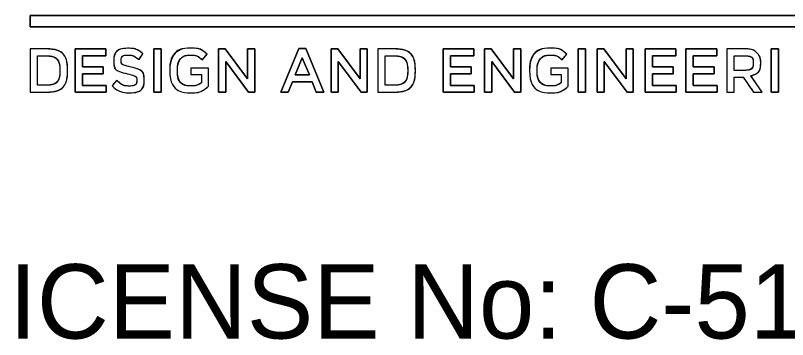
# Model space of a CAD drawing. Extents: x 1674550 to 1676250, y 1328139 to 1330492.
# Drawn here: x 1676168.88 to 1676209.45, y 1329059.45 to 1329076.5 of the extents above; entities that cross this region are included whole.
import ezdxf

# ---------------------------------------------------------------- set-up
doc = ezdxf.new("R2010")
doc.units = 0
doc.layers.add('Sheet Plan CELL', color=7, linetype='Continuous')

msp = doc.modelspace()

# ---------------------------------------------------------------- linework, layer by layer
at = {"layer": 'Sheet Plan CELL'}
for p, q in [((1676175.371, 1329074.182), (1676175.577, 1329074.484)), ((1676178.701, 1329074.166), (1676178.943, 1329074.467)), ((1676197.607, 1329074.166), (1676197.85, 1329074.467)), ((1676174.042, 1329074.11), (1676174.042, 1329074.104)), ((1676174.425, 1329074.14), (1676174.425, 1329074.146)), ((1676207.647, 1329073.997), (1676207.647, 1329073.99)), ((1676208.036, 1329074.013), (1676208.036, 1329074.02)), ((1676171.214, 1329073.601), (1676171.214, 1329073.595)), ((1676171.616, 1329073.601), (1676171.616, 1329073.607)), ((1676176.983, 1329073.601), (1676176.983, 1329073.595)), ((1676177.384, 1329073.601), (1676177.384, 1329073.607)), ((1676189.488, 1329073.601), (1676189.488, 1329073.595)), ((1676189.89, 1329073.601), (1676189.89, 1329073.607)), ((1676195.889, 1329073.601), (1676195.889, 1329073.595)), ((1676196.29, 1329073.601), (1676196.29, 1329073.607)), ((1676174.185, 1329073.082), (1676173.955, 1329072.796)), ((1676175.259, 1329073.079), (1676175.259, 1329073.072)), ((1676175.642, 1329073.111), (1676175.642, 1329073.118))]:
    msp.add_line(p, q, dxfattribs=at)
for points in [[(1676230.5, 1329075.895), (1676169.657, 1329075.895), (1676169.657, 1329076.499), (1676230.5, 1329076.499), (1676230.5, 1329075.895)], [(1676230.5, 1329076.499), (1676169.657, 1329076.499), (1676169.657, 1329075.895), (1676230.5, 1329075.895), (1676230.5, 1329076.499)], [(1676183.775, 1329074.753), (1676184.13, 1329074.753), (1676185.089, 1329072.465), (1676184.684, 1329072.465), (1676184.463, 1329073.014), (1676183.433, 1329073.014), (1676183.209, 1329072.465), (1676182.817, 1329072.465), (1676183.775, 1329074.753)], [(1676182.817, 1329072.465), (1676183.209, 1329072.465), (1676183.433, 1329073.014), (1676184.463, 1329073.014), (1676184.684, 1329072.465), (1676185.089, 1329072.465), (1676184.13, 1329074.753), (1676183.775, 1329074.753), (1676182.817, 1329072.465)], [(1676170.458, 1329074.737), (1676169.646, 1329074.737), (1676169.646, 1329072.465), (1676170.458, 1329072.465)], [(1676170.458, 1329072.829), (1676170.029, 1329072.829), (1676170.029, 1329074.373), (1676170.458, 1329074.373)], [(1676172.017, 1329074.737), (1676173.632, 1329074.737), (1676173.632, 1329074.38), (1676172.399, 1329074.38), (1676172.399, 1329073.789), (1676173.492, 1329073.789), (1676173.492, 1329073.432), (1676172.399, 1329073.432), (1676172.399, 1329072.822), (1676173.647, 1329072.822), (1676173.647, 1329072.465), (1676172.017, 1329072.465), (1676172.017, 1329074.737)], [(1676172.017, 1329072.465), (1676173.647, 1329072.465), (1676173.647, 1329072.822), (1676172.399, 1329072.822), (1676172.399, 1329073.432), (1676173.492, 1329073.432), (1676173.492, 1329073.789), (1676172.399, 1329073.789), (1676172.399, 1329074.38), (1676173.632, 1329074.38), (1676173.632, 1329074.737), (1676172.017, 1329074.737), (1676172.017, 1329072.465)], [(1676176.145, 1329074.737), (1676176.528, 1329074.737), (1676176.528, 1329072.465), (1676176.145, 1329072.465), (1676176.145, 1329074.737)], [(1676176.145, 1329072.465), (1676176.528, 1329072.465), (1676176.528, 1329074.737), (1676176.145, 1329074.737), (1676176.145, 1329072.465)], [(1676179.55, 1329074.737), (1676179.904, 1329074.737), (1676181.072, 1329073.166), (1676181.072, 1329074.737), (1676181.448, 1329074.737), (1676181.448, 1329072.465), (1676181.127, 1329072.465), (1676179.926, 1329074.081), (1676179.926, 1329072.465), (1676179.55, 1329072.465), (1676179.55, 1329074.737)], [(1676179.55, 1329072.465), (1676179.926, 1329072.465), (1676179.926, 1329074.081), (1676181.127, 1329072.465), (1676181.448, 1329072.465), (1676181.448, 1329074.737), (1676181.072, 1329074.737), (1676181.072, 1329073.166), (1676179.904, 1329074.737), (1676179.55, 1329074.737), (1676179.55, 1329072.465)], [(1676185.462, 1329074.737), (1676185.817, 1329074.737), (1676186.983, 1329073.166), (1676186.983, 1329074.737), (1676187.36, 1329074.737), (1676187.36, 1329072.465), (1676187.04, 1329072.465), (1676185.838, 1329074.081), (1676185.838, 1329072.465), (1676185.462, 1329072.465), (1676185.462, 1329074.737)], [(1676185.462, 1329072.465), (1676185.838, 1329072.465), (1676185.838, 1329074.081), (1676187.04, 1329072.465), (1676187.36, 1329072.465), (1676187.36, 1329074.737), (1676186.983, 1329074.737), (1676186.983, 1329073.166), (1676185.817, 1329074.737), (1676185.462, 1329074.737), (1676185.462, 1329072.465)], [(1676188.732, 1329074.737), (1676187.92, 1329074.737), (1676187.92, 1329072.465), (1676188.732, 1329072.465)], [(1676188.732, 1329072.829), (1676188.303, 1329072.829), (1676188.303, 1329074.373), (1676188.732, 1329074.373)], [(1676191.349, 1329074.737), (1676192.964, 1329074.737), (1676192.964, 1329074.38), (1676191.732, 1329074.38), (1676191.732, 1329073.789), (1676192.824, 1329073.789), (1676192.824, 1329073.432), (1676191.732, 1329073.432), (1676191.732, 1329072.822), (1676192.98, 1329072.822), (1676192.98, 1329072.465), (1676191.349, 1329072.465), (1676191.349, 1329074.737)], [(1676191.349, 1329072.465), (1676192.98, 1329072.465), (1676192.98, 1329072.822), (1676191.732, 1329072.822), (1676191.732, 1329073.432), (1676192.824, 1329073.432), (1676192.824, 1329073.789), (1676191.732, 1329073.789), (1676191.732, 1329074.38), (1676192.964, 1329074.38), (1676192.964, 1329074.737), (1676191.349, 1329074.737), (1676191.349, 1329072.465)], [(1676193.527, 1329074.737), (1676193.882, 1329074.737), (1676195.049, 1329073.166), (1676195.049, 1329074.737), (1676195.425, 1329074.737), (1676195.425, 1329072.465), (1676195.105, 1329072.465), (1676193.904, 1329074.081), (1676193.904, 1329072.465), (1676193.527, 1329072.465), (1676193.527, 1329074.737)], [(1676193.527, 1329072.465), (1676193.904, 1329072.465), (1676193.904, 1329074.081), (1676195.105, 1329072.465), (1676195.425, 1329072.465), (1676195.425, 1329074.737), (1676195.049, 1329074.737), (1676195.049, 1329073.166), (1676193.882, 1329074.737), (1676193.527, 1329074.737), (1676193.527, 1329072.465)], [(1676198.446, 1329074.737), (1676198.829, 1329074.737), (1676198.829, 1329072.465), (1676198.446, 1329072.465), (1676198.446, 1329074.737)], [(1676198.446, 1329072.465), (1676198.829, 1329072.465), (1676198.829, 1329074.737), (1676198.446, 1329074.737), (1676198.446, 1329072.465)], [(1676199.442, 1329074.737), (1676199.797, 1329074.737), (1676200.964, 1329073.166), (1676200.964, 1329074.737), (1676201.341, 1329074.737), (1676201.341, 1329072.465), (1676201.02, 1329072.465), (1676199.819, 1329074.081), (1676199.819, 1329072.465), (1676199.442, 1329072.465), (1676199.442, 1329074.737)], [(1676199.442, 1329072.465), (1676199.819, 1329072.465), (1676199.819, 1329074.081), (1676201.02, 1329072.465), (1676201.341, 1329072.465), (1676201.341, 1329074.737), (1676200.964, 1329074.737), (1676200.964, 1329073.166), (1676199.797, 1329074.737), (1676199.442, 1329074.737), (1676199.442, 1329072.465)], [(1676201.962, 1329074.737), (1676203.578, 1329074.737), (1676203.578, 1329074.38), (1676202.345, 1329074.38), (1676202.345, 1329073.789), (1676203.438, 1329073.789), (1676203.438, 1329073.432), (1676202.345, 1329073.432), (1676202.345, 1329072.822), (1676203.593, 1329072.822), (1676203.593, 1329072.465), (1676201.962, 1329072.465), (1676201.962, 1329074.737)], [(1676201.962, 1329072.465), (1676203.593, 1329072.465), (1676203.593, 1329072.822), (1676202.345, 1329072.822), (1676202.345, 1329073.432), (1676203.438, 1329073.432), (1676203.438, 1329073.789), (1676202.345, 1329073.789), (1676202.345, 1329074.38), (1676203.578, 1329074.38), (1676203.578, 1329074.737), (1676201.962, 1329074.737), (1676201.962, 1329072.465)], [(1676204.109, 1329074.737), (1676205.724, 1329074.737), (1676205.724, 1329074.38), (1676204.492, 1329074.38), (1676204.492, 1329073.789), (1676205.585, 1329073.789), (1676205.585, 1329073.432), (1676204.492, 1329073.432), (1676204.492, 1329072.822), (1676205.74, 1329072.822), (1676205.74, 1329072.465), (1676204.109, 1329072.465), (1676204.109, 1329074.737)], [(1676204.109, 1329072.465), (1676205.74, 1329072.465), (1676205.74, 1329072.822), (1676204.492, 1329072.822), (1676204.492, 1329073.432), (1676205.585, 1329073.432), (1676205.585, 1329073.789), (1676204.492, 1329073.789), (1676204.492, 1329074.38), (1676205.724, 1329074.38), (1676205.724, 1329074.737), (1676204.109, 1329074.737), (1676204.109, 1329072.465)], [(1676207.227, 1329074.737), (1676206.256, 1329074.737), (1676206.256, 1329072.465), (1676206.639, 1329072.465), (1676206.639, 1329073.257), (1676207.118, 1329073.257), (1676207.654, 1329072.465), (1676208.108, 1329072.465), (1676207.52, 1329073.325)], [(1676207.199, 1329073.611), (1676206.639, 1329073.611), (1676206.639, 1329074.373), (1676207.196, 1329074.373)], [(1676208.59, 1329074.737), (1676208.972, 1329074.737), (1676208.972, 1329072.465), (1676208.59, 1329072.465), (1676208.59, 1329074.737)], [(1676208.59, 1329072.465), (1676208.972, 1329072.465), (1676208.972, 1329074.737), (1676208.59, 1329074.737), (1676208.59, 1329072.465)], [(1676184.323, 1329073.367), (1676183.947, 1329074.276), (1676183.573, 1329073.367), (1676184.323, 1329073.367)], [(1676183.573, 1329073.367), (1676183.947, 1329074.276), (1676184.323, 1329073.367), (1676183.573, 1329073.367)], [(1676179.021, 1329072.78), (1676179.021, 1329073.734), (1676178.094, 1329073.734), (1676178.094, 1329073.387), (1676178.651, 1329073.387), (1676178.651, 1329072.962)], [(1676197.927, 1329072.78), (1676197.927, 1329073.734), (1676197, 1329073.734), (1676197, 1329073.387), (1676197.557, 1329073.387), (1676197.557, 1329072.962)]]:
    msp.add_lwpolyline(points, dxfattribs=at)
for points, degree in [([(1676173.955, 1329072.796), (1676173.955, 1329072.796), (1676174.185, 1329073.082), (1676174.185, 1329073.082), (1676174.394, 1329072.894), (1676174.605, 1329072.787), (1676174.873, 1329072.787), (1676175.11, 1329072.787), (1676175.259, 1329072.903), (1676175.259, 1329073.072), (1676175.259, 1329073.072), (1676175.259, 1329073.079), (1676175.259, 1329073.079), (1676175.259, 1329073.241), (1676175.172, 1329073.328), (1676174.767, 1329073.426), (1676174.304, 1329073.543), (1676174.042, 1329073.685), (1676174.042, 1329074.104), (1676174.042, 1329074.104), (1676174.042, 1329074.11), (1676174.042, 1329074.11), (1676174.042, 1329074.5), (1676174.353, 1329074.769), (1676174.786, 1329074.769), (1676175.104, 1329074.769), (1676175.356, 1329074.669), (1676175.577, 1329074.484), (1676175.577, 1329074.484), (1676175.371, 1329074.182), (1676175.371, 1329074.182), (1676175.175, 1329074.334), (1676174.979, 1329074.416), (1676174.78, 1329074.416), (1676174.556, 1329074.416), (1676174.425, 1329074.295), (1676174.425, 1329074.146), (1676174.425, 1329074.146), (1676174.425, 1329074.14), (1676174.425, 1329074.14), (1676174.425, 1329073.964), (1676174.525, 1329073.887), (1676174.945, 1329073.783), (1676175.405, 1329073.666), (1676175.642, 1329073.494), (1676175.642, 1329073.118), (1676175.642, 1329073.118), (1676175.642, 1329073.111), (1676175.642, 1329073.111), (1676175.642, 1329072.686), (1676175.321, 1329072.433), (1676174.864, 1329072.433), (1676174.531, 1329072.433), (1676174.217, 1329072.553), (1676173.955, 1329072.796)], 3), ([(1676175.577, 1329074.484), (1676175.356, 1329074.669), (1676175.104, 1329074.769), (1676174.786, 1329074.769), (1676174.353, 1329074.769), (1676174.042, 1329074.5), (1676174.042, 1329074.11)], 3), ([(1676176.983, 1329073.595), (1676176.983, 1329073.595), (1676176.983, 1329073.601), (1676176.983, 1329073.601), (1676176.983, 1329074.237), (1676177.449, 1329074.776), (1676178.106, 1329074.776), (1676178.486, 1329074.776), (1676178.719, 1329074.665), (1676178.943, 1329074.467), (1676178.943, 1329074.467), (1676178.701, 1329074.166), (1676178.701, 1329074.166), (1676178.532, 1329074.315), (1676178.368, 1329074.409), (1676178.091, 1329074.409), (1676177.689, 1329074.409), (1676177.384, 1329074.042), (1676177.384, 1329073.607), (1676177.384, 1329073.607), (1676177.384, 1329073.601), (1676177.384, 1329073.601), (1676177.384, 1329073.134), (1676177.68, 1329072.79), (1676178.125, 1329072.79), (1676178.33, 1329072.79), (1676178.517, 1329072.858), (1676178.651, 1329072.962), (1676178.651, 1329072.962), (1676178.651, 1329073.387), (1676178.651, 1329073.387), (1676178.651, 1329073.387), (1676178.094, 1329073.387), (1676178.094, 1329073.387), (1676178.094, 1329073.387), (1676178.094, 1329073.734), (1676178.094, 1329073.734), (1676178.094, 1329073.734), (1676179.021, 1329073.734), (1676179.021, 1329073.734), (1676179.021, 1329073.734), (1676179.021, 1329072.78), (1676179.021, 1329072.78), (1676178.806, 1329072.589), (1676178.498, 1329072.426), (1676178.112, 1329072.426), (1676177.431, 1329072.426), (1676176.983, 1329072.933), (1676176.983, 1329073.595)], 3), ([(1676178.943, 1329074.467), (1676178.719, 1329074.665), (1676178.486, 1329074.776), (1676178.106, 1329074.776), (1676177.449, 1329074.776), (1676176.983, 1329074.237), (1676176.983, 1329073.601)], 3), ([(1676195.889, 1329073.595), (1676195.889, 1329073.595), (1676195.889, 1329073.601), (1676195.889, 1329073.601), (1676195.889, 1329074.237), (1676196.356, 1329074.776), (1676197.012, 1329074.776), (1676197.392, 1329074.776), (1676197.625, 1329074.665), (1676197.85, 1329074.467), (1676197.85, 1329074.467), (1676197.607, 1329074.166), (1676197.607, 1329074.166), (1676197.439, 1329074.315), (1676197.274, 1329074.409), (1676196.997, 1329074.409), (1676196.595, 1329074.409), (1676196.29, 1329074.042), (1676196.29, 1329073.607), (1676196.29, 1329073.607), (1676196.29, 1329073.601), (1676196.29, 1329073.601), (1676196.29, 1329073.134), (1676196.586, 1329072.79), (1676197.031, 1329072.79), (1676197.236, 1329072.79), (1676197.423, 1329072.858), (1676197.557, 1329072.962), (1676197.557, 1329072.962), (1676197.557, 1329073.387), (1676197.557, 1329073.387), (1676197.557, 1329073.387), (1676197, 1329073.387), (1676197, 1329073.387), (1676197, 1329073.387), (1676197, 1329073.734), (1676197, 1329073.734), (1676197, 1329073.734), (1676197.927, 1329073.734), (1676197.927, 1329073.734), (1676197.927, 1329073.734), (1676197.927, 1329072.78), (1676197.927, 1329072.78), (1676197.713, 1329072.589), (1676197.404, 1329072.426), (1676197.019, 1329072.426), (1676196.337, 1329072.426), (1676195.889, 1329072.933), (1676195.889, 1329073.595)], 3), ([(1676197.85, 1329074.467), (1676197.625, 1329074.665), (1676197.392, 1329074.776), (1676197.012, 1329074.776), (1676196.356, 1329074.776), (1676195.889, 1329074.237), (1676195.889, 1329073.601)], 3), ([(1676169.646, 1329074.737), (1676169.646, 1329074.737), (1676170.458, 1329074.737), (1676170.458, 1329074.737), (1676171.143, 1329074.737), (1676171.616, 1329074.247), (1676171.616, 1329073.607), (1676171.616, 1329073.607), (1676171.616, 1329073.601), (1676171.616, 1329073.601), (1676171.616, 1329072.962), (1676171.143, 1329072.465), (1676170.458, 1329072.465), (1676170.458, 1329072.465), (1676169.646, 1329072.465), (1676169.646, 1329072.465), (1676169.646, 1329072.465), (1676169.646, 1329074.737), (1676169.646, 1329074.737)], 3), ([(1676170.029, 1329074.373), (1676170.029, 1329074.373), (1676170.029, 1329072.829), (1676170.029, 1329072.829), (1676170.029, 1329072.829), (1676170.458, 1329072.829), (1676170.458, 1329072.829), (1676170.915, 1329072.829), (1676171.214, 1329073.15), (1676171.214, 1329073.595), (1676171.214, 1329073.595), (1676171.214, 1329073.601), (1676171.214, 1329073.601), (1676171.214, 1329074.046), (1676170.915, 1329074.373), (1676170.458, 1329074.373), (1676170.458, 1329074.373), (1676170.029, 1329074.373), (1676170.029, 1329074.373)], 3), ([(1676171.616, 1329073.607), (1676171.616, 1329074.247), (1676171.143, 1329074.737), (1676170.458, 1329074.737)], 2), ([(1676170.458, 1329074.373), (1676170.915, 1329074.373), (1676171.214, 1329074.046), (1676171.214, 1329073.601)], 2), ([(1676174.425, 1329074.146), (1676174.425, 1329074.295), (1676174.556, 1329074.416), (1676174.78, 1329074.416), (1676174.979, 1329074.416), (1676175.175, 1329074.334), (1676175.371, 1329074.182)], 3), ([(1676177.384, 1329073.607), (1676177.384, 1329074.042), (1676177.689, 1329074.409), (1676178.091, 1329074.409), (1676178.368, 1329074.409), (1676178.532, 1329074.315), (1676178.701, 1329074.166)], 3), ([(1676187.92, 1329074.737), (1676187.92, 1329074.737), (1676188.732, 1329074.737), (1676188.732, 1329074.737), (1676189.417, 1329074.737), (1676189.89, 1329074.247), (1676189.89, 1329073.607), (1676189.89, 1329073.607), (1676189.89, 1329073.601), (1676189.89, 1329073.601), (1676189.89, 1329072.962), (1676189.417, 1329072.465), (1676188.732, 1329072.465), (1676188.732, 1329072.465), (1676187.92, 1329072.465), (1676187.92, 1329072.465), (1676187.92, 1329072.465), (1676187.92, 1329074.737), (1676187.92, 1329074.737)], 3), ([(1676188.303, 1329074.373), (1676188.303, 1329074.373), (1676188.303, 1329072.829), (1676188.303, 1329072.829), (1676188.303, 1329072.829), (1676188.732, 1329072.829), (1676188.732, 1329072.829), (1676189.19, 1329072.829), (1676189.488, 1329073.15), (1676189.488, 1329073.595), (1676189.488, 1329073.595), (1676189.488, 1329073.601), (1676189.488, 1329073.601), (1676189.488, 1329074.046), (1676189.19, 1329074.373), (1676188.732, 1329074.373), (1676188.732, 1329074.373), (1676188.303, 1329074.373), (1676188.303, 1329074.373)], 3), ([(1676189.89, 1329073.607), (1676189.89, 1329074.247), (1676189.417, 1329074.737), (1676188.732, 1329074.737)], 2), ([(1676188.732, 1329074.373), (1676189.19, 1329074.373), (1676189.488, 1329074.046), (1676189.488, 1329073.601)], 2), ([(1676196.29, 1329073.607), (1676196.29, 1329074.042), (1676196.595, 1329074.409), (1676196.997, 1329074.409), (1676197.274, 1329074.409), (1676197.439, 1329074.315), (1676197.607, 1329074.166)], 3), ([(1676206.256, 1329074.737), (1676206.256, 1329074.737), (1676207.227, 1329074.737), (1676207.227, 1329074.737), (1676207.501, 1329074.737), (1676207.716, 1329074.652), (1676207.856, 1329074.51), (1676207.971, 1329074.386), (1676208.036, 1329074.218), (1676208.036, 1329074.02), (1676208.036, 1329074.02), (1676208.036, 1329074.013), (1676208.036, 1329074.013), (1676208.036, 1329073.64), (1676207.822, 1329073.416), (1676207.52, 1329073.325), (1676207.52, 1329073.325), (1676208.108, 1329072.465), (1676208.108, 1329072.465), (1676208.108, 1329072.465), (1676207.654, 1329072.465), (1676207.654, 1329072.465), (1676207.654, 1329072.465), (1676207.118, 1329073.257), (1676207.118, 1329073.257), (1676207.118, 1329073.257), (1676206.639, 1329073.257), (1676206.639, 1329073.257), (1676206.639, 1329073.257), (1676206.639, 1329072.465), (1676206.639, 1329072.465), (1676206.639, 1329072.465), (1676206.256, 1329072.465), (1676206.256, 1329072.465), (1676206.256, 1329072.465), (1676206.256, 1329074.737), (1676206.256, 1329074.737)], 3), ([(1676207.199, 1329073.611), (1676207.473, 1329073.611), (1676207.647, 1329073.76), (1676207.647, 1329073.99), (1676207.647, 1329073.99), (1676207.647, 1329073.997), (1676207.647, 1329073.997), (1676207.647, 1329074.24), (1676207.479, 1329074.373), (1676207.196, 1329074.373), (1676207.196, 1329074.373), (1676206.639, 1329074.373), (1676206.639, 1329074.373), (1676206.639, 1329074.373), (1676206.639, 1329073.611), (1676206.639, 1329073.611), (1676206.639, 1329073.611), (1676207.199, 1329073.611), (1676207.199, 1329073.611)], 3), ([(1676207.196, 1329074.373), (1676207.479, 1329074.373), (1676207.647, 1329074.24), (1676207.647, 1329073.997)], 2), ([(1676208.036, 1329074.02), (1676208.036, 1329074.218), (1676207.971, 1329074.386), (1676207.856, 1329074.51), (1676207.716, 1329074.652), (1676207.501, 1329074.737), (1676207.227, 1329074.737)], 3), ([(1676174.042, 1329074.104), (1676174.042, 1329073.685), (1676174.304, 1329073.543), (1676174.767, 1329073.426), (1676175.172, 1329073.328), (1676175.259, 1329073.241), (1676175.259, 1329073.079)], 3), ([(1676175.642, 1329073.118), (1676175.642, 1329073.494), (1676175.405, 1329073.666), (1676174.945, 1329073.783), (1676174.525, 1329073.887), (1676174.425, 1329073.964), (1676174.425, 1329074.14)], 3), ([(1676207.647, 1329073.99), (1676207.647, 1329073.76), (1676207.473, 1329073.611), (1676207.199, 1329073.611)], 2), ([(1676207.52, 1329073.325), (1676207.822, 1329073.416), (1676208.036, 1329073.64), (1676208.036, 1329074.013)], 2), ([(1676170.458, 1329072.465), (1676171.143, 1329072.465), (1676171.616, 1329072.962), (1676171.616, 1329073.601)], 2), ([(1676171.214, 1329073.595), (1676171.214, 1329073.15), (1676170.915, 1329072.829), (1676170.458, 1329072.829)], 2), ([(1676176.983, 1329073.595), (1676176.983, 1329072.933), (1676177.431, 1329072.426), (1676178.112, 1329072.426), (1676178.498, 1329072.426), (1676178.806, 1329072.589), (1676179.021, 1329072.78)], 3), ([(1676178.651, 1329072.962), (1676178.517, 1329072.858), (1676178.33, 1329072.79), (1676178.125, 1329072.79), (1676177.68, 1329072.79), (1676177.384, 1329073.134), (1676177.384, 1329073.601)], 3), ([(1676188.732, 1329072.465), (1676189.417, 1329072.465), (1676189.89, 1329072.962), (1676189.89, 1329073.601)], 2), ([(1676189.488, 1329073.595), (1676189.488, 1329073.15), (1676189.19, 1329072.829), (1676188.732, 1329072.829)], 2), ([(1676195.889, 1329073.595), (1676195.889, 1329072.933), (1676196.337, 1329072.426), (1676197.019, 1329072.426), (1676197.404, 1329072.426), (1676197.713, 1329072.589), (1676197.927, 1329072.78)], 3), ([(1676197.557, 1329072.962), (1676197.423, 1329072.858), (1676197.236, 1329072.79), (1676197.031, 1329072.79), (1676196.586, 1329072.79), (1676196.29, 1329073.134), (1676196.29, 1329073.601)], 3), ([(1676173.955, 1329072.796), (1676174.217, 1329072.553), (1676174.531, 1329072.433), (1676174.864, 1329072.433), (1676175.321, 1329072.433), (1676175.642, 1329072.686), (1676175.642, 1329073.111)], 3), ([(1676175.259, 1329073.072), (1676175.259, 1329072.903), (1676175.11, 1329072.787), (1676174.873, 1329072.787), (1676174.605, 1329072.787), (1676174.394, 1329072.894), (1676174.185, 1329073.082)], 3)]:
    msp.add_open_spline(points, degree=degree, dxfattribs=at)

# ---------------------------------------------------------------- texts
msp.add_text('NC FIRM LICENSE No: C-5176', height=3.90762, rotation=360, dxfattribs=at).set_placement((1676142.426, 1329059.506))

doc.saveas('drawing.dxf')
